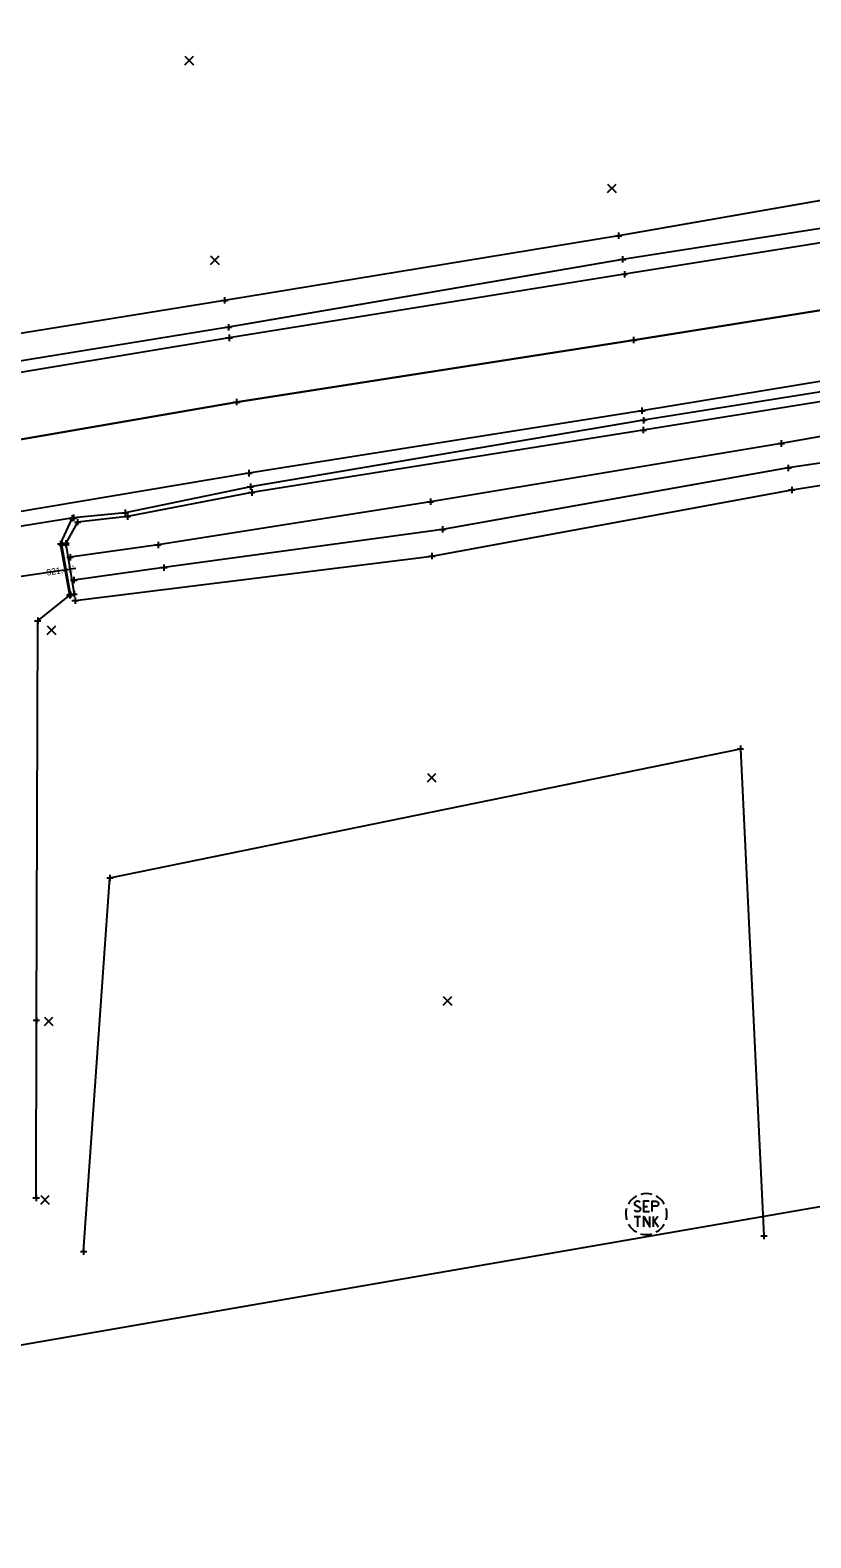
# Model space of a CAD drawing. Extents: x 1386013 to 1389776, y 604170 to 607009.
# Drawn here: x 1386562.3 to 1386684, y 604497.8 to 604732.7 of the extents above; entities that cross this region are included whole.
import ezdxf

# ---------------------------------------------------------------- set-up
doc = ezdxf.new("R2010")
doc.units = 0
for name, color, linetype in [('DR_X_Headwall', 7, 'Continuous'), ('DR_X_Storm_Sewer', 7, 'Continuous'), ('DV_X_Text', 7, 'Continuous'), ('PM_X_CL_Double_Solid', 7, 'Continuous'), ('PV_X_COP', 7, 'Continuous'), ('PV_X_Driveway', 7, 'Continuous'), ('PV_X_EOP', 7, 'Continuous'), ('PV_X_Shoulder', 7, 'Continuous'), ('SC_Scratch1', 7, 'Continuous'), ('SH_Cut_Line', 7, 'Continuous'), ('SV_X_Random_Point', 7, 'Continuous'), ('SV_X_Toe_of_Slope', 7, 'Continuous'), ('SV_X_Top_of_Bank', 7, 'Continuous'), ('UT_X_Leach_Bed', 7, 'Continuous'), ('UT_X_Sanitary_Cells', 7, 'Continuous')]:
    doc.layers.add(name, color=color, linetype=linetype)

msp = doc.modelspace()

# ---------------------------------------------------------------- linework, layer by layer
at = {"layer": 'DR_X_Headwall'}
msp.add_lwpolyline([(1386567.29, 604652.56), (1386567.89, 604652.6), (1386569.17, 604644.87), (1386568.61, 604644.79)], close=True, dxfattribs=at)
at = {"layer": 'DR_X_Storm_Sewer'}
msp.add_line((1386541.08, 604644.72), (1386569.43, 604648.91), dxfattribs=at)
at = {"layer": 'DV_X_Text'}
for p, q in [((1386653.53, 604700.72), (1386654.53, 604700.72)), ((1386654.03, 604701.22), (1386654.03, 604700.22)), ((1386654.03, 604700.72), (1386654.03, 604700.72)), ((1386654.65, 604697.52), (1386654.65, 604696.52)), ((1386654.15, 604697.02), (1386655.15, 604697.02)), ((1386654.65, 604697.02), (1386654.65, 604697.02)), ((1386654.93, 604695.21), (1386654.93, 604694.21)), ((1386654.43, 604694.71), (1386655.43, 604694.71)), ((1386654.93, 604694.71), (1386654.93, 604694.71)), ((1386592.1, 604690.63), (1386593.1, 604690.63)), ((1386592.6, 604691.13), (1386592.6, 604690.13)), ((1386592.6, 604690.63), (1386592.6, 604690.63)), ((1386592.72, 604686.44), (1386593.72, 604686.44)), ((1386593.22, 604686.94), (1386593.22, 604685.94)), ((1386593.22, 604686.44), (1386593.22, 604686.44)), ((1386592.84, 604684.8), (1386593.84, 604684.8)), ((1386593.34, 604685.3), (1386593.34, 604684.3)), ((1386593.34, 604684.8), (1386593.34, 604684.8)), ((1386655.83, 604684.46), (1386656.83, 604684.46)), ((1386656.33, 604684.96), (1386656.33, 604683.96)), ((1386656.33, 604684.46), (1386656.33, 604684.46)), ((1386593.98, 604674.79), (1386594.98, 604674.79)), ((1386594.48, 604675.29), (1386594.48, 604674.29)), ((1386594.48, 604674.79), (1386594.48, 604674.79)), ((1386657.65, 604673.94), (1386657.65, 604672.94)), ((1386657.15, 604673.44), (1386658.15, 604673.44)), ((1386657.39, 604671.95), (1386658.39, 604671.95)), ((1386657.65, 604673.44), (1386657.65, 604673.44)), ((1386657.89, 604672.45), (1386657.89, 604671.45)), ((1386657.89, 604671.95), (1386657.89, 604671.95)), ((1386657.37, 604670.42), (1386658.37, 604670.42)), ((1386657.87, 604670.92), (1386657.87, 604669.92)), ((1386657.87, 604670.42), (1386657.87, 604670.42)), ((1386678.88, 604668.33), (1386679.88, 604668.33)), ((1386679.38, 604668.83), (1386679.38, 604667.83)), ((1386679.38, 604668.33), (1386679.38, 604668.33)), ((1386679.97, 604664.52), (1386680.97, 604664.52)), ((1386680.47, 604665.02), (1386680.47, 604664.02)), ((1386680.47, 604664.52), (1386680.47, 604664.52)), ((1386595.91, 604663.71), (1386596.91, 604663.71)), ((1386596.41, 604664.21), (1386596.41, 604663.21)), ((1386596.41, 604663.71), (1386596.41, 604663.71)), ((1386596.66, 604662.1), (1386596.66, 604661.1)), ((1386596.16, 604661.6), (1386597.16, 604661.6)), ((1386596.35, 604660.69), (1386597.35, 604660.69)), ((1386596.66, 604661.6), (1386596.66, 604661.6)), ((1386596.85, 604661.19), (1386596.85, 604660.19)), ((1386596.85, 604660.69), (1386596.85, 604660.69)), ((1386624.7, 604659.75), (1386624.7, 604658.75)), ((1386680.51, 604661.09), (1386681.51, 604661.09)), ((1386681.01, 604661.59), (1386681.01, 604660.59)), ((1386681.01, 604661.09), (1386681.01, 604661.09)), ((1386569.07, 604657.26), (1386569.07, 604656.26)), ((1386576.62, 604657.52), (1386577.62, 604657.52)), ((1386577.12, 604658.02), (1386577.12, 604657.02)), ((1386577.12, 604657.52), (1386577.12, 604657.52)), ((1386577.49, 604657.45), (1386577.49, 604656.45)), ((1386624.2, 604659.25), (1386625.2, 604659.25)), ((1386624.7, 604659.25), (1386624.7, 604659.25)), ((1386568.36, 604656.66), (1386569.36, 604656.66)), ((1386568.57, 604656.76), (1386569.57, 604656.76)), ((1386568.86, 604657.16), (1386568.86, 604656.16)), ((1386568.86, 604656.66), (1386568.86, 604656.66)), ((1386569.07, 604656.76), (1386569.07, 604656.76)), ((1386569.23, 604656.09), (1386570.23, 604656.09)), ((1386569.73, 604656.59), (1386569.73, 604655.59)), ((1386569.73, 604656.09), (1386569.73, 604656.09)), ((1386576.99, 604656.95), (1386577.99, 604656.95)), ((1386577.49, 604656.95), (1386577.49, 604656.95)), ((1386626.07, 604654.95), (1386627.07, 604654.95)), ((1386626.57, 604655.45), (1386626.57, 604654.45)), ((1386626.57, 604654.95), (1386626.57, 604654.95)), ((1386566.57, 604652.68), (1386567.57, 604652.68)), ((1386566.79, 604652.56), (1386567.79, 604652.56)), ((1386567.07, 604653.18), (1386567.07, 604652.18)), ((1386567.07, 604652.68), (1386567.07, 604652.68)), ((1386567.29, 604653.06), (1386567.29, 604652.06)), ((1386567.29, 604652.56), (1386567.29, 604652.56)), ((1386567.39, 604652.6), (1386568.39, 604652.6)), ((1386567.4, 604652.78), (1386568.4, 604652.78)), ((1386567.89, 604653.1), (1386567.89, 604652.1)), ((1386567.89, 604652.6), (1386567.89, 604652.6)), ((1386567.9, 604653.28), (1386567.9, 604652.28)), ((1386567.9, 604652.78), (1386567.9, 604652.78)), ((1386582.26, 604653.02), (1386582.26, 604652.02)), ((1386568.05, 604650.6), (1386569.05, 604650.6)), ((1386568.55, 604651.1), (1386568.55, 604650.1)), ((1386568.55, 604650.6), (1386568.55, 604650.6)), ((1386581.76, 604652.52), (1386582.76, 604652.52)), ((1386582.26, 604652.52), (1386582.26, 604652.52)), ((1386624.42, 604650.78), (1386625.42, 604650.78)), ((1386624.92, 604651.28), (1386624.92, 604650.28)), ((1386624.92, 604650.78), (1386624.92, 604650.78)), ((1386582.66, 604648.99), (1386583.66, 604648.99)), ((1386583.16, 604649.49), (1386583.16, 604648.49)), ((1386583.16, 604648.99), (1386583.16, 604648.99)), ((1386568.64, 604647.05), (1386569.64, 604647.05)), ((1386569.14, 604647.55), (1386569.14, 604646.55)), ((1386569.14, 604647.05), (1386569.14, 604647.05)), ((1386567.99, 604644.68), (1386568.99, 604644.68)), ((1386568.11, 604644.79), (1386569.11, 604644.79)), ((1386568.49, 604645.18), (1386568.49, 604644.18)), ((1386568.49, 604644.68), (1386568.49, 604644.68)), ((1386568.61, 604645.29), (1386568.61, 604644.29)), ((1386568.61, 604644.79), (1386568.61, 604644.79)), ((1386568.67, 604644.87), (1386569.67, 604644.87)), ((1386568.84, 604643.85), (1386569.84, 604643.85)), ((1386569.17, 604645.37), (1386569.17, 604644.37)), ((1386569.17, 604644.87), (1386569.17, 604644.87)), ((1386569.34, 604644.35), (1386569.34, 604643.35)), ((1386569.34, 604643.85), (1386569.34, 604643.85)), ((1386563.51, 604641.2), (1386563.51, 604640.2)), ((1386563.01, 604640.7), (1386564.01, 604640.7)), ((1386563.51, 604640.7), (1386563.51, 604640.7)), ((1386672.5, 604620.77), (1386673.5, 604620.77)), ((1386673, 604621.27), (1386673, 604620.27)), ((1386673, 604620.77), (1386673, 604620.77)), ((1386574.77, 604601.13), (1386574.77, 604600.13)), ((1386574.27, 604600.63), (1386575.27, 604600.63)), ((1386574.77, 604600.63), (1386574.77, 604600.63)), ((1386562.8, 604578.44), (1386563.8, 604578.44)), ((1386563.3, 604578.94), (1386563.3, 604577.94)), ((1386563.3, 604578.44), (1386563.3, 604578.44)), ((1386562.77, 604550.76), (1386563.77, 604550.76)), ((1386563.27, 604551.26), (1386563.27, 604550.26)), ((1386563.27, 604550.76), (1386563.27, 604550.76)), ((1386676.17, 604544.84), (1386677.17, 604544.84)), ((1386676.67, 604545.34), (1386676.67, 604544.34)), ((1386676.67, 604544.84), (1386676.67, 604544.84)), ((1386570.17, 604542.41), (1386571.17, 604542.41)), ((1386570.67, 604542.91), (1386570.67, 604541.91)), ((1386570.67, 604542.41), (1386570.67, 604542.41))]:
    msp.add_line(p, q, dxfattribs=at)
at = {"layer": 'PM_X_CL_Double_Solid'}
msp.add_lwpolyline([(1386468.73, 604654.2), (1386537.3, 604664.92), (1386594.48, 604674.79), (1386656.33, 604684.46), (1386713.85, 604693.61), (1386771.72, 604702.67), (1386828.75, 604712.1), (1386886.1, 604721.12), (1386941.92, 604730.57), (1387000.37, 604739.9)], dxfattribs=at)
at = {"layer": 'PV_X_COP'}
msp.add_lwpolyline([(1387000.37, 604739.9), (1386941.92, 604730.57), (1386886.1, 604721.12), (1386828.75, 604712.1), (1386771.72, 604702.67), (1386713.85, 604693.61), (1386656.33, 604684.46), (1386594.48, 604674.79), (1386537.3, 604664.92), (1386475.24, 604654.93), (1386414.35, 604644.79), (1386366.58, 604636.8), (1386295.22, 604625.24), (1386269.2, 604620.76)], dxfattribs=at)
at = {"layer": 'PV_X_Driveway'}
msp.add_lwpolyline([(1386563.27, 604550.76), (1386563.3, 604578.44), (1386563.51, 604640.7), (1386568.49, 604644.68), (1386567.07, 604652.68), (1386568.86, 604656.66)], dxfattribs=at)
at = {"layer": 'PV_X_EOP'}
for points in [[(1386999.09, 604750.97), (1386941.41, 604741.04), (1386884.67, 604731.59), (1386826.82, 604722.39), (1386770.2, 604713.13), (1386713.15, 604704.01), (1386654.93, 604694.71), (1386593.34, 604684.8), (1386535.41, 604675.21), (1386469.16, 604664.5), (1386392.09, 604651.62), (1386332.26, 604641.82), (1386267.39, 604631.1)], [(1387002.9, 604729.17), (1386943.42, 604719.4), (1386887.14, 604710.13), (1386830.12, 604700.78), (1386772.1, 604691.69), (1386715.3, 604682.94), (1386657.65, 604673.44), (1386596.41, 604663.71), (1386538.98, 604654.04), (1386477.51, 604644.07), (1386414.44, 604633.64), (1386368.83, 604626.04), (1386296.84, 604614.17), (1386270.69, 604609.87)]]:
    msp.add_lwpolyline(points, dxfattribs=at)
at = {"layer": 'PV_X_Shoulder'}
for points in [[(1386998.59, 604752.7), (1386940.97, 604743.32), (1386884.65, 604733.55), (1386826.54, 604724.64), (1386769.98, 604715.15), (1386712.42, 604706.07), (1386654.65, 604697.02), (1386593.22, 604686.44), (1386535.13, 604677.03), (1386468.95, 604665.92), (1386392.3, 604653.36), (1386331.76, 604643.52), (1386267.19, 604632.89)], [(1386985.4, 604722.84), (1386965.11, 604719.46), (1386961.9, 604720.55), (1386943.38, 604718.17), (1386887.62, 604708.36), (1386830.36, 604699.21), (1386772.3, 604689.74), (1386715.56, 604681.18), (1386657.89, 604671.95), (1386596.66, 604661.6), (1386577.12, 604657.52), (1386569.07, 604656.76), (1386539.67, 604652.01), (1386479.08, 604642.34), (1386478.07, 604642.14), (1386414.53, 604632.43), (1386369.38, 604624.9), (1386296.82, 604613.19), (1386270.73, 604608.85)]]:
    msp.add_lwpolyline(points, dxfattribs=at)
at = {"layer": 'SH_Cut_Line'}
msp.add_lwpolyline([(1386387.56, 604497.79), (1386350, 604714.56), (1386685.02, 604772.59), (1386722.57, 604555.82)], close=True, dxfattribs=at)
at = {"layer": 'SV_X_Random_Point'}
for p, q in [((1386586.43, 604727.35), (1386587.76, 604728.69)), ((1386586.43, 604728.69), (1386587.76, 604727.35)), ((1386652.31, 604707.43), (1386653.64, 604708.76)), ((1386652.31, 604708.76), (1386653.64, 604707.43)), ((1386590.43, 604696.25), (1386591.76, 604697.59)), ((1386590.43, 604697.59), (1386591.76, 604696.25)), ((1386564.99, 604638.58), (1386566.32, 604639.91)), ((1386564.99, 604639.91), (1386566.32, 604638.58)), ((1386624.24, 604615.58), (1386625.57, 604616.91)), ((1386624.24, 604616.91), (1386625.57, 604615.58)), ((1386626.69, 604580.79), (1386628.02, 604582.13)), ((1386626.69, 604582.13), (1386628.02, 604580.79)), ((1386564.56, 604577.61), (1386565.89, 604578.94)), ((1386564.56, 604578.94), (1386565.89, 604577.61)), ((1386563.98, 604549.79), (1386565.31, 604551.13)), ((1386563.98, 604551.13), (1386565.31, 604549.79))]:
    msp.add_line(p, q, dxfattribs=at)
at = {"layer": 'SV_X_Toe_of_Slope'}
for points in [[(1387571.9, 604860.13), (1387513.17, 604847.9), (1387455.73, 604837.69), (1387401.04, 604827.65), (1387339.29, 604815.83), (1387289.1, 604807.74), (1387230.03, 604798.15), (1387173.08, 604787.71), (1387123.84, 604780.19), (1387058.58, 604768.72), (1386997.09, 604757.11), (1386939.93, 604748.73), (1386883.98, 604739), (1386826.09, 604728.82), (1386769.04, 604719.03), (1386711.7, 604710.77), (1386654.03, 604700.72), (1386592.6, 604690.63), (1386534.1, 604681.18), (1386480.03, 604672.89), (1386465.51, 604671.66), (1386391.46, 604656.56), (1386330.8, 604647.36), (1386266.18, 604637.16)], [(1386963.2, 604712.53), (1386913.42, 604706.16), (1386867.12, 604697.62), (1386823.42, 604690.47), (1386772.44, 604683.92), (1386725.64, 604676.53), (1386679.38, 604668.33), (1386624.7, 604659.25), (1386582.26, 604652.52), (1386568.55, 604650.6)], [(1386963.56, 604710.65), (1386914.69, 604700.42), (1386869.02, 604692.96), (1386824.5, 604685.91), (1386773.81, 604678.46), (1386726.54, 604671.29), (1386680.47, 604664.52), (1386626.57, 604654.95), (1386583.16, 604648.99), (1386569.14, 604647.05)]]:
    msp.add_lwpolyline(points, dxfattribs=at)
at = {"layer": 'SV_X_Top_of_Bank'}
for points in [[(1386966.8, 604706.78), (1386963.95, 604717.89), (1386959.21, 604718.9), (1386943.67, 604716.74), (1386887.58, 604706.91), (1386830.61, 604697.95), (1386772.45, 604688.91), (1386715.75, 604679.7), (1386657.87, 604670.42), (1386596.85, 604660.69), (1386577.49, 604656.95), (1386569.73, 604656.09), (1386567.9, 604652.78)], [(1386569.34, 604643.85), (1386624.92, 604650.78), (1386681.01, 604661.09), (1386736.97, 604670), (1386789.91, 604677.7), (1386846.74, 604688.33), (1386893.85, 604694.05), (1386943.3, 604701.92), (1386966.95, 604706.82)]]:
    msp.add_lwpolyline(points, dxfattribs=at)
at = {"layer": 'UT_X_Leach_Bed'}
msp.add_lwpolyline([(1386570.67, 604542.41), (1386574.77, 604600.63), (1386673, 604620.77), (1386676.67, 604544.84)], dxfattribs=at)
at = {"layer": 'UT_X_Sanitary_Cells'}
msp.add_line((1386658.36, 604548.24), (1386658.36, 604548.24), dxfattribs=at)
for points in [[(1386657.36, 604550.12), (1386657.34, 604550.15), (1386657.3, 604550.17), (1386657.19, 604550.21), (1386657.05, 604550.24), (1386656.95, 604550.24), (1386656.91, 604550.24), (1386656.75, 604550.2), (1386656.61, 604550.12), (1386656.52, 604550.02), (1386656.49, 604549.92), (1386656.49, 604549.85), (1386656.52, 604549.75), (1386656.62, 604549.66), (1386657.31, 604549.28), (1386657.38, 604549.23), (1386657.4, 604549.18), (1386657.43, 604549.1), (1386657.43, 604549.03), (1386657.41, 604548.95), (1386657.4, 604548.9), (1386657.38, 604548.84), (1386657.35, 604548.79), (1386657.33, 604548.75), (1386657.29, 604548.71), (1386657.25, 604548.69), (1386657.2, 604548.66), (1386657.16, 604548.65), (1386657.05, 604548.64), (1386656.87, 604548.64), (1386656.76, 604548.66), (1386656.59, 604548.75), (1386656.49, 604548.83)], [(1386658.77, 604550.24), (1386657.9, 604550.24), (1386657.9, 604548.64), (1386658.84, 604548.64)], [(1386657.9, 604549.44), (1386658.52, 604549.44)], [(1386659.28, 604548.64), (1386659.28, 604550.24), (1386659.88, 604550.24), (1386659.95, 604550.22), (1386660.03, 604550.2), (1386660.07, 604550.17), (1386660.11, 604550.15), (1386660.16, 604550.09), (1386660.2, 604550.02), (1386660.22, 604549.92), (1386660.22, 604549.77), (1386660.21, 604549.72), (1386660.18, 604549.64), (1386660.13, 604549.56), (1386660.08, 604549.52), (1386660.05, 604549.49), (1386659.98, 604549.47), (1386659.88, 604549.46), (1386659.28, 604549.46)], [(1386656.46, 604547.84), (1386657.45, 604547.84)], [(1386656.96, 604547.84), (1386656.96, 604546.24)], [(1386657.96, 604546.24), (1386657.96, 604547.84), (1386658.9, 604546.24), (1386658.9, 604547.84)], [(1386659.4, 604547.84), (1386659.4, 604546.24)], [(1386660.13, 604547.84), (1386659.4, 604546.82)], [(1386659.64, 604547.15), (1386660.26, 604546.24)]]:
    msp.add_lwpolyline(points, dxfattribs=at)
for start, end in [(118.9866, 150.9578), (73.9409, 105.9366), (28.9866, 60.9578), (164.0021, 196.0591), (344.0021, 15.9979), (208.9866, 240.9578), (253.9409, 285.9366), (298.9866, 331.0134)]:
    msp.add_arc((1386658.35, 604548.24), 3.2, start, end, dxfattribs=at)

# ---------------------------------------------------------------- texts
at = {"layer": 'SC_Scratch1'}
msp.add_text("921.41'", height=1, rotation=8.4033, dxfattribs=at).set_placement((1386564.95, 604647.74))

doc.saveas('drawing.dxf')
